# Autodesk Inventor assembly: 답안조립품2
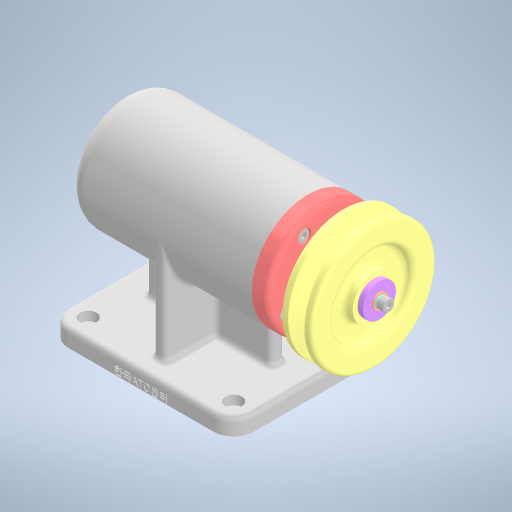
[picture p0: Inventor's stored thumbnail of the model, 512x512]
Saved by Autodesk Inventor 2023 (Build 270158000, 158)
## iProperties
Created: 2026-08
Part Number: 답안조립품2
Document SubType Name: Assembly
Designer: 4강의실
Author: 4강의실
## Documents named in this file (14)
- C:\Users\kimgi\Downloads\760803V1001\답안조립품2.iam
- C:\Users\kimgi\Downloads\760803V1001\부품.ipt
- C:\Users\kimgi\Desktop\760603V1008\6각 구멍붙이 볼트 M4x12.ipt
- C:\Users\kimgi\Desktop\760603V1008\V 벨트 풀리.ipt
- C:\Users\kimgi\Desktop\760603V1008\깊은 홈 볼 베어링 6004.ipt
- C:\Users\kimgi\Desktop\760603V1008\스러스트 볼 베어링 51202.ipt
- C:\Users\kimgi\Desktop\760603V1008\스프링 와셔 M4.ipt
- C:\Users\kimgi\Desktop\760603V1008\어댑터 슬리브.ipt
- C:\Users\kimgi\Desktop\760603V1008\엔드 캡.ipt
- C:\Users\kimgi\Desktop\760603V1008\오일 실 20 32 5.ipt
- C:\Users\kimgi\Desktop\760603V1008\축.ipt
- C:\Users\kimgi\Desktop\760603V1008\커버.ipt
- C:\Users\kimgi\Desktop\760603V1008\평 와셔 M4.ipt
- C:\Users\kimgi\Desktop\760603V1008\평행 키 5x5x16.ipt
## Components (7 placed, 2 different names)
1. V 벨트 풀리:1 — 각도:3
2. 6각 구멍붙이 볼트 M4x12:2
3. 6각 구멍붙이 볼트 M4x12:7
4. 6각 구멍붙이 볼트 M4x12:3
5. 6각 구멍붙이 볼트 M4x12:4
6. 6각 구멍붙이 볼트 M4x12:5
7. 6각 구멍붙이 볼트 M4x12:6
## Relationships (1: Angle 1)
- 각도:3 [Angle]: V 벨트 풀리:1
